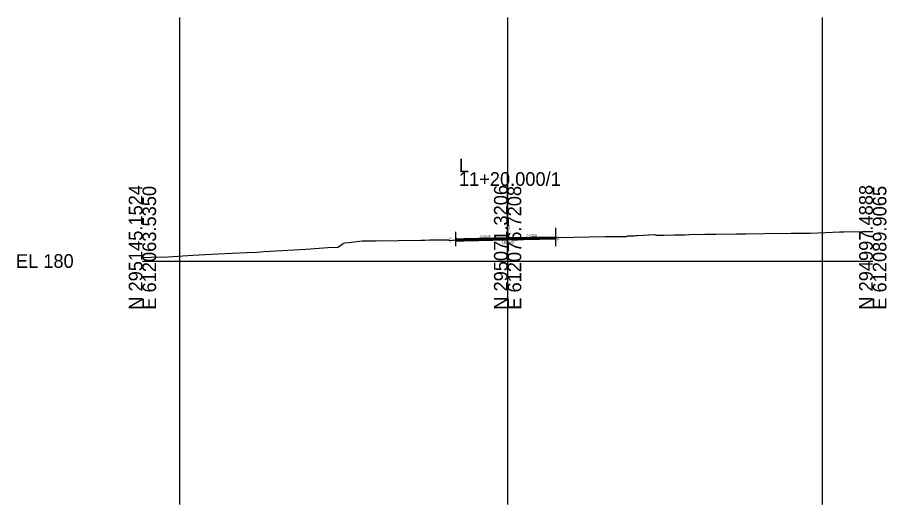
# Model space of a CAD drawing. Extents: x -81 to 616364, y 450 to 299952.
# Drawn here: x 535426.7 to 535605.2, y 117798.4 to 117898.4 of the extents above; entities that cross this region are included whole.
import ezdxf

# ---------------------------------------------------------------- set-up
doc = ezdxf.new("R2010")
doc.units = 0
for name, color, linetype in [('Exist XS Ground Line', 7, 'Continuous'), ('Old_Level_10', 7, 'Continuous'), ('Old_Level_6', 7, 'Continuous'), ('Old_Level_63', 7, 'Continuous'), ('Prop XS Dump Level', 7, 'Continuous'), ('Prop XS Earthwork Shape', 7, 'Continuous'), ('Prop XS EOT Tick Mark', 7, 'Continuous'), ('Prop XS Exc Vertical Line 1', 7, 'Continuous'), ('Prop XS Exc Vertical Line 2', 7, 'Continuous'), ('Prop XS Exc Vertical Line 3', 7, 'Continuous'), ('Prop XS Finish Grade Pavement', 7, 'Continuous'), ('Prop XS Side Slope Text', 7, 'Continuous'), ('Prop XS Subgrade Concrete', 7, 'Continuous'), ('Prop XS Subgrade Earthwork', 7, 'Continuous')]:
    doc.layers.add(name, color=color, linetype=linetype)

msp = doc.modelspace()

# ---------------------------------------------------------------- linework, layer by layer
at = {"layer": 'Exist XS Ground Line'}
for points in [[(535452.36, 117849.09), (535454.15, 117849.14), (535457.58, 117849.21), (535462.69, 117849.53), (535467.81, 117849.83), (535473.75, 117850.11), (535475.84, 117850.21), (535477.39, 117850.29), (535485.94, 117850.78), (535490.45, 117851.16), (535492.49, 117851.21), (535493.05, 117851.58), (535493.45, 117851.87), (535493.83, 117852.11), (535494.73, 117852.19), (535497.5, 117852.5), (535500.33, 117852.52), (535509.57, 117852.64), (535510.35, 117852.64), (535511.32, 117852.69), (535511.48, 117852.69), (535512.63, 117852.72), (535515.2, 117852.73), (535515.37, 117852.57), (535515.96, 117852.63), (535516.18, 117852.63), (535521.26, 117852.8), (535523.78, 117852.86), (535525.28, 117852.89), (535526.83, 117852.93), (535527.38, 117852.95), (535528.44, 117852.98), (535530.99, 117853.06), (535533.3, 117853.13), (535533.75, 117853.13), (535534.61, 117853.15), (535547.43, 117853.38), (535548.17, 117853.4), (535550.83, 117853.42), (535551.39, 117853.4), (535551.8, 117853.36), (535552.04, 117853.51), (535552.47, 117853.5), (535553.27, 117853.52), (535553.66, 117853.58), (535553.98, 117853.63), (535557.63, 117853.78), (535557.86, 117853.69), (535559.49, 117853.69), (535561.65, 117853.74), (535563.74, 117853.75), (535564.73, 117853.8), (535567.84, 117853.87), (535570.14, 117853.87), (535574.36, 117853.91), (535576.25, 117853.95), (535580.1, 117853.99), (535585.59, 117854.05), (535588.65, 117854.08), (535588.88, 117854.08), (535589.41, 117854.09), (535589.55, 117854.09), (535592.62, 117854.22), (535594.09, 117854.3), (535595.55, 117854.34)], [(535595.55, 117854.34), (535596.45, 117854.36), (535600.27, 117854.42), (535601.28, 117854.44), (535601.62, 117854.44), (535602.36, 117854.42)]]:
    msp.add_lwpolyline(points, dxfattribs=at)
at = {"layer": 'Old_Level_10'}
msp.add_line((535537.26, 117852.91), (535537.26, 117853.2), dxfattribs=at)
at = {"layer": 'Old_Level_6'}
for p, q in [((535516.76, 117851.42), (535516.76, 117854.33)), ((535537.26, 117853.34), (535537.26, 117855.14)), ((535537.26, 117851.43), (535537.26, 117852.91))]:
    msp.add_line(p, q, dxfattribs=at)
at = {"layer": 'Old_Level_63'}
for p, q in [((535527.36, 117848.36), (535527.36, 117866.59)), ((535452.36, 117848.36), (535527.36, 117848.36)), ((535527.36, 117848.36), (535602.36, 117848.36))]:
    msp.add_line(p, q, dxfattribs=at)
at = {"layer": 'Prop XS Dump Level'}
for p, q in [((535516.76, 117852.88), (535518.36, 117852.91)), ((535518.36, 117852.91), (535527.36, 117853.09)), ((535527.36, 117853.09), (535537.26, 117853.29))]:
    msp.add_line(p, q, dxfattribs=at)
at = {"layer": 'Prop XS Earthwork Shape'}
for points in [[(535516.76, 117852.5), (535518.36, 117852.53), (535527.36, 117852.71), (535537.26, 117852.91), (535537.26, 117853.2), (535534.61, 117853.15), (535533.75, 117853.13), (535533.3, 117853.13), (535530.99, 117853.06), (535528.44, 117852.98), (535527.38, 117852.95), (535526.83, 117852.93), (535525.28, 117852.89), (535523.78, 117852.86), (535521.26, 117852.8), (535516.77, 117852.65)], [(535518.36, 117852.53), (535527.36, 117852.71), (535537.26, 117852.91), (535537.26, 117853.2), (535534.61, 117853.15), (535533.75, 117853.13), (535533.3, 117853.13), (535530.99, 117853.06), (535528.44, 117852.98), (535527.38, 117852.95), (535526.83, 117852.93), (535525.28, 117852.89), (535523.78, 117852.86), (535521.26, 117852.8), (535516.77, 117852.65), (535516.76, 117852.5)], [(535518.36, 117852.53), (535527.36, 117852.71), (535537.26, 117852.91), (535537.26, 117853.2), (535534.61, 117853.15), (535533.75, 117853.13), (535533.3, 117853.13), (535530.99, 117853.06), (535528.44, 117852.98), (535527.38, 117852.95), (535526.83, 117852.93), (535525.28, 117852.89), (535523.78, 117852.86), (535521.26, 117852.8), (535516.77, 117852.65), (535516.76, 117852.5)], [(535537.26, 117852.91), (535537.26, 117853.2), (535534.61, 117853.15), (535533.75, 117853.13), (535533.3, 117853.13), (535530.99, 117853.06), (535528.44, 117852.98), (535527.38, 117852.95), (535526.83, 117852.93), (535525.28, 117852.89), (535523.78, 117852.86), (535521.26, 117852.8), (535516.77, 117852.65), (535516.76, 117852.5), (535518.36, 117852.53), (535527.36, 117852.71)], [(535516.76, 117852.5), (535518.36, 117852.53), (535527.36, 117852.71), (535537.26, 117852.91), (535537.26, 117853.2), (535534.61, 117853.15), (535533.75, 117853.13), (535533.3, 117853.13), (535530.99, 117853.06), (535528.44, 117852.98), (535527.38, 117852.95), (535526.83, 117852.93), (535525.28, 117852.89), (535523.78, 117852.86), (535521.26, 117852.8), (535516.77, 117852.65)], [(535516.76, 117852.5), (535518.36, 117852.53), (535527.36, 117852.71), (535537.26, 117852.91), (535537.26, 117853.2), (535534.61, 117853.15), (535533.75, 117853.13), (535533.3, 117853.13), (535530.99, 117853.06), (535528.44, 117852.98), (535527.38, 117852.95), (535526.83, 117852.93), (535525.28, 117852.89), (535523.78, 117852.86), (535521.26, 117852.8), (535516.77, 117852.65)], [(535527.36, 117852.95), (535527.36, 117852.71), (535518.36, 117852.53), (535516.76, 117852.5), (535516.77, 117852.65), (535521.26, 117852.8), (535523.78, 117852.86), (535525.28, 117852.89), (535526.83, 117852.93)], [(535528.44, 117852.98), (535530.99, 117853.06), (535533.3, 117853.13), (535533.75, 117853.13), (535534.61, 117853.15), (535537.26, 117853.2), (535537.26, 117852.91), (535527.36, 117852.71), (535527.36, 117852.95), (535527.38, 117852.95)]]:
    msp.add_lwpolyline(points, close=True, dxfattribs=at)
at = {"layer": 'Prop XS EOT Tick Mark'}
for p, q in [((535516.76, 117853.18), (535516.76, 117852.88)), ((535537.26, 117853.29), (535537.26, 117853.59))]:
    msp.add_line(p, q, dxfattribs=at)
at = {"layer": 'Prop XS Exc Vertical Line 1'}
msp.add_line((535459.94, 117898.36), (535459.94, 117798.36), dxfattribs=at)
at = {"layer": 'Prop XS Exc Vertical Line 2'}
msp.add_line((535527.36, 117898.36), (535527.36, 117798.36), dxfattribs=at)
at = {"layer": 'Prop XS Exc Vertical Line 3'}
msp.add_line((535591.96, 117898.36), (535591.96, 117798.36), dxfattribs=at)
at = {"layer": 'Prop XS Finish Grade Pavement'}
for p, q in [((535518.36, 117852.91), (535516.76, 117852.88)), ((535527.36, 117853.09), (535518.36, 117852.91)), ((535537.26, 117853.29), (535527.36, 117853.09))]:
    msp.add_line(p, q, dxfattribs=at)
at = {"layer": 'Prop XS Subgrade Concrete'}
for p, q in [((535516.76, 117852.7), (535516.76, 117852.88)), ((535537.26, 117853.29), (535537.26, 117853.11))]:
    msp.add_line(p, q, dxfattribs=at)
at = {"layer": 'Prop XS Subgrade Earthwork'}
for p, q in [((535516.77, 117852.65), (535516.76, 117852.5)), ((535516.76, 117852.5), (535516.76, 117852.65)), ((535516.76, 117852.5), (535518.36, 117852.53)), ((535518.36, 117852.53), (535527.36, 117852.71)), ((535527.36, 117852.71), (535537.26, 117852.91)), ((535537.26, 117852.91), (535537.26, 117853.2))]:
    msp.add_line(p, q, dxfattribs=at)

# ---------------------------------------------------------------- texts
at = {"layer": 'Old_Level_63'}
for s, p in [('L', (535517.36, 117866.59)), ('11+20.000/1', (535517.36, 117863.79)), ('EL 180', (535426.37, 117846.96))]:
    msp.add_text(s, height=2.8, dxfattribs=at).set_placement(p)
for s, p in [('N 295145.1524', (535452.36, 117838.36)), ('E 612063.5350', (535455.16, 117838.37)), ('N 295071.3206', (535527.36, 117838.36)), ('E 612076.7208', (535530.16, 117838.37)), ('N 294997.4888', (535602.36, 117838.37)), ('E 612089.9065', (535605.16, 117838.37))]:
    msp.add_text(s, height=2.8, rotation=90, dxfattribs=at).set_placement(p)
at = {"layer": 'Prop XS Side Slope Text'}
for s, rotation, p in [(' 184.723', 90, (535527.86, 117853.09)), ('-Y1-', 90, (535515.9, 117852.06)), ('0.0200', 1.1458, (535521.79, 117853.13)), ('0.0200', 1.1458, (535531.24, 117853.32)), ('-Y2-', 90, (535538.01, 117852.3))]:
    msp.add_text(s, height=0.5, rotation=rotation, dxfattribs=at).set_placement(p)
msp.add_text('184.583', height=0.5, dxfattribs=at).set_placement((535526.17, 117851.91))

doc.saveas('drawing.dxf')
